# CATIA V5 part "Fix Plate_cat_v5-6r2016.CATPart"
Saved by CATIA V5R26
Part number: Fix Plate
Bounding box of the stored display mesh (mm): x -45 to 45, y -150 to 150, z -40 to 230
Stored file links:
  D:\_Deepak\CATIA\CATIA V5 2015 Parts Files\Tutorial Files\Tutorials\c16_catia_v5_6r2016_tut\Slide Curve\Fix Plate_cat_v5-6r2012.CATPart
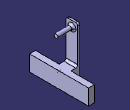
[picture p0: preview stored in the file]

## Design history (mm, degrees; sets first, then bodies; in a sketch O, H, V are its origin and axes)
Body1 (main body)
  Sketch1 on yz-plane, origin (0, 0, 0), H (0, 1, 0), V (0, 0, 1)
    line L1 (150, 40) -> (150, -40)
    line L2 (150, -40) -> (-150, -40)
    line L3 (-150, -40) -> (-150, 40)
    line L4 (-150, 40) -> (150, 40)
    length L4 = 300
    length L1 = 80
    vertical: L1 V, L3 V
    horizontal: L2 H, L4 H
    equidistance: L1 L3 O, L2 L4 O
  Pad1: profile Sketch1, direction (1, 0, 0), length 30
  Point1: type OnCurve, Support edge [face of Pad1 from Sketch1.L4 | end face of Pad1], Ratio 0.5
  Sketch2 on start face of Pad1, origin (0, 0, 0), H (0, -1, 0), V (0, 0, 1)
    circle A1 centre (0, 200) radius 10
    point P1 (0, 200)
    reference projected line E1 (-150, 40) -> (150, 40) from edge [start face of Pad1 | face of Pad1 from Sketch1.L4]
    radius A1 = 10
    distance E1 P1 = 160
    coincidence: P1 V
  Pad2: profile Sketch2, direction (1, 0, 0), length 45, mirrored extent
  Sketch3 on start face of Pad2, origin (-45, 0, 0), H (0, -1, 0), V (0, 0, 1)
    line L1 (30, -40) -> (-30, -40)
    line L2 (-30, -40) -> (-30, 230)
    line L3 (-30, 230) -> (30, 230)
    line L4 (30, 230) -> (30, -40)
    reference projected line E1 (-150, 40) -> (150, 40) from edge [start face of Pad1 | face of Pad1 from Sketch1.L4]
    length L3 = 60
    distance V L2 = 30
    distance E1 L3 = 190
    horizontal: L1 H, L3 H
    vertical: L2 V, L4 V
  Pad3: profile Sketch3, direction (1, 0, 0), length 10
  Sketch4 on end face of Pad3, origin (-35, 0, 0), H (0, 1, 0), V (0, 0, 1)
    line L1 (-30, 40) -> (30, 40)
    line L2 (30, 40) -> (30, -40)
    line L3 (30, -40) -> (-30, -40)
    line L4 (-30, -40) -> (-30, 40)
    reference projected line E1 (150, 40) -> (-150, 40) from edge [face of Pad1 from Sketch1.L4 | end face of Pad1]
    reference projected line E2 (-30, -40) -> (-30, 230) from edge [end face of Pad3 | face of Pad3 from Sketch3.L4]
    reference projected line E3 (-150, -40) -> (150, -40) from edge [face of Pad1 from Sketch1.L2 | end face of Pad1]
    reference projected line E4 (30, 230) -> (30, -40) from edge [end face of Pad3 | face of Pad3 from Sketch3.L2]
    horizontal: L1 H, L3 H
    vertical: L2 V, L4 V
    coincidence: L1 E1, L4 E2, L3 E3, L2 E4
  Pad4: profile Sketch4, direction (1, 0, 0), up to the existing solid (limit type 2)
  Fillet1: radius 10, on edge [face of Pad3 from Sketch3.L3 | face of Pad3]; edge [face of Pad2 from Sketch2.A1 | end face of Pad3]; edge [face of Pad4 | face of Pad3 from Sketch3.L3]; edge [end face of Pad3 | face of Pad1]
